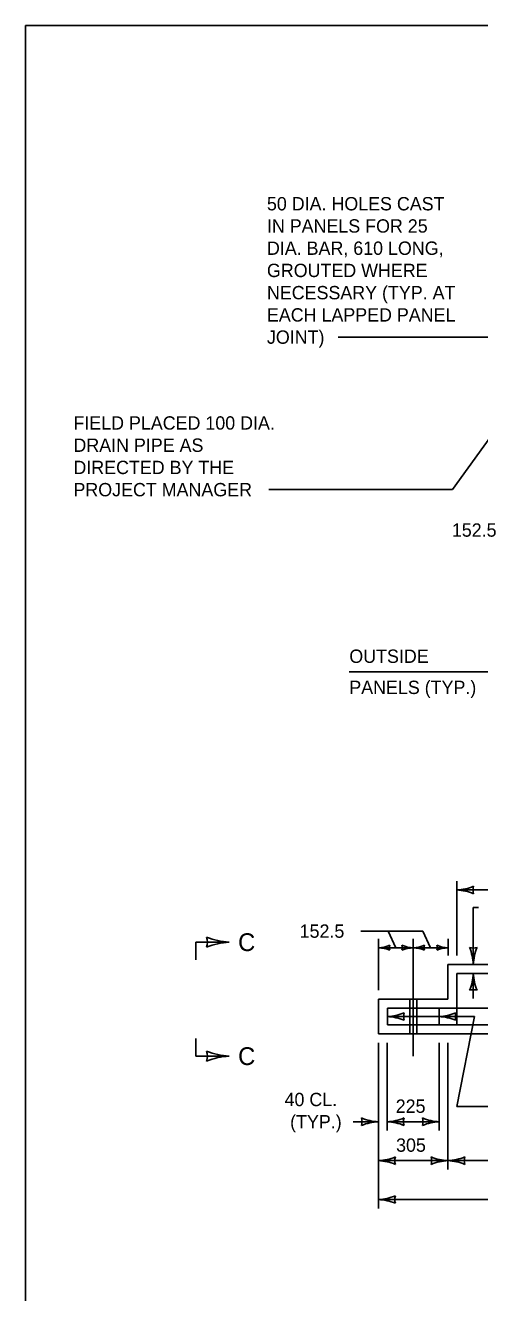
# Model space of a CAD drawing. Extents: x 49991.4 to 50021, y 49987.6 to 50011.4.
# Drawn here: x 49999.38 to 50001.43, y 49993.3 to 49999 of the extents above; entities that cross this region are included whole.
import ezdxf

# ---------------------------------------------------------------- set-up
doc = ezdxf.new("R2010")
doc.units = 0
for name, color, linetype in [('Level 1', 7, 'Continuous'), ('Level 2', 7, 'Continuous'), ('Level 3', 7, 'Continuous'), ('Level 4', 7, 'Continuous'), ('Level 5', 7, 'Continuous'), ('Level 6', 7, 'Continuous')]:
    doc.layers.add(name, color=color, linetype=linetype)

msp = doc.modelspace()

# ---------------------------------------------------------------- linework, layer by layer
at = {"layer": 'Level 1'}
for p, q in [((50003.3142, 49994.7753), (50001.283, 49994.7753)), ((50001.283, 49994.7753), (50001.283, 49994.619)), ((50001.323, 49994.7352), (50001.323, 49994.5029)), ((50003.2741, 49994.7352), (50001.323, 49994.7352)), ((50001.283, 49994.619), (50000.9705, 49994.619)), ((50000.9705, 49994.619), (50000.9705, 49994.4628)), ((50001.0105, 49994.579), (50001.0105, 49994.5029)), ((50001.0105, 49994.579), (50001.6735, 49994.579)), ((50001.2428, 49994.5029), (50001.2428, 49994.579)), ((50000.9705, 49994.4628), (50003.6267, 49994.4628)), ((50001.0105, 49994.5029), (50003.5866, 49994.5029))]:
    msp.add_line(p, q, dxfattribs=at)
msp.add_lwpolyline([(49999.3835, 49998.9992), (50016.7501, 49998.9992), (50016.7501, 49987.7988), (49999.3835, 49987.7988)], close=True, dxfattribs=at)
at = {"layer": 'Level 3'}
for p, q in [((50000.7897, 49997.5969), (50001.6157, 49997.5969)), ((50001.5149, 49997.2046), (50001.3035, 49996.9108)), ((50000.4775, 49996.9108), (50001.3035, 49996.9108)), ((50000.8395, 49996.0916), (50001.7038, 49996.0916)), ((50001.3223, 49994.8153), (50001.3223, 49995.1502)), ((50003.2753, 49995.1102), (50001.3223, 49995.1102)), ((50001.3969, 49995.031), (50001.42, 49995.031)), ((50001.3969, 49994.7753), (50001.3969, 49995.031)), ((50001.17, 49994.9252), (50000.8914, 49994.9252)), ((50001.0136, 49994.9252), (50001.0486, 49994.8502)), ((50001.17, 49994.9252), (50001.205, 49994.8502)), ((50000.9706, 49994.659), (50000.9706, 49994.8902)), ((50001.2832, 49994.8153), (50001.2832, 49994.8902)), ((50001.1268, 49994.8502), (50000.9706, 49994.8502)), ((50001.2832, 49994.8502), (50001.1268, 49994.8502)), ((50001.3969, 49994.6228), (50001.3969, 49994.7352)), ((50001.4028, 49994.541), (50001.0105, 49994.541)), ((50001.4028, 49994.541), (50001.323, 49994.1368)), ((50000.9705, 49994.4228), (50000.9705, 49993.6777)), ((50001.0097, 49994.4228), (50001.0097, 49994.0278)), ((50001.2441, 49994.4228), (50001.2441, 49994.0278)), ((50001.283, 49994.4228), (50001.283, 49993.8527)), ((50001.323, 49994.1368), (50001.5507, 49994.1368)), ((50000.9705, 49994.0678), (50000.8571, 49994.0678)), ((50001.2441, 49994.0678), (50001.0097, 49994.0678)), ((50000.9705, 49993.8927), (50001.283, 49993.8927)), ((50003.3142, 49993.8927), (50001.283, 49993.8927)), ((50003.6267, 49993.7177), (50000.9705, 49993.7177))]:
    msp.add_line(p, q, dxfattribs=at)
for centre, radius, start, end in [((50001.3131, 49995.3323), 0.2223, 272.3605, 292.544), ((50001.3108, 49994.8775), 0.233, 67.9228, 87.1727), ((50001.4505, 49995.1102), 0.0548, 162.1388, 197.8612), ((50000.1287, 49994.8754), 0.073, 342.1388, 17.8612), ((50000.315, 49995.1857), 0.3107, 247.9228, 267.1727), ((50000.3118, 49994.5792), 0.2964, 92.3605, 112.544), ((50000.9645, 49994.9983), 0.1482, 272.3605, 292.544), ((50001.056, 49994.8502), 0.0365, 162.1388, 197.8612), ((50001.0413, 49994.8502), 0.0365, 342.1388, 17.8612), ((50001.1345, 49995.0053), 0.1553, 247.9228, 267.1727), ((50001.1207, 49994.9983), 0.1482, 272.3605, 292.544), ((50001.2123, 49994.8502), 0.0365, 162.1388, 197.8612), ((50001.1977, 49994.8502), 0.0365, 342.1388, 17.8612), ((50001.2908, 49995.0053), 0.1553, 247.9228, 267.1727), ((50000.9629, 49994.6951), 0.1553, 67.9228, 87.1727), ((50001.1329, 49994.7021), 0.1482, 92.3605, 112.544), ((50001.1191, 49994.6951), 0.1553, 67.9228, 87.1727), ((50001.2893, 49994.7021), 0.1482, 92.3605, 112.544), ((50001.3969, 49994.9035), 0.0548, 252.1388, 287.8612), ((50001.1642, 49994.7638), 0.233, 2.8273, 22.0772), ((50001.619, 49994.7661), 0.2223, 157.456, 177.6395), ((50001.1748, 49994.7444), 0.2223, 337.456, 357.6395), ((50001.6296, 49994.7467), 0.233, 182.8273, 202.0772), ((50001.3969, 49994.607), 0.0548, 72.1388, 107.8612), ((50001.0013, 49994.7631), 0.2223, 272.3605, 292.544), ((50000.999, 49994.3083), 0.233, 67.9228, 87.1727), ((50001.1387, 49994.541), 0.0548, 162.1388, 197.8612), ((50001.2336, 49994.7631), 0.2223, 272.3605, 292.544), ((50001.2313, 49994.3083), 0.233, 67.9228, 87.1727), ((50001.371, 49994.541), 0.0548, 162.1388, 197.8612), ((50000.1287, 49994.3628), 0.073, 342.1388, 17.8612), ((50000.315, 49994.6731), 0.3107, 247.9228, 267.1727), ((50000.3118, 49994.0666), 0.2964, 92.3605, 112.544), ((50000.8423, 49994.0678), 0.0548, 342.1388, 17.8612), ((50000.982, 49994.3005), 0.233, 247.9228, 267.1727), ((50000.9797, 49993.8457), 0.2223, 92.3605, 112.544), ((50001.0005, 49994.2899), 0.2223, 272.3605, 292.544), ((50000.9982, 49993.8351), 0.233, 67.9228, 87.1727), ((50001.1379, 49994.0678), 0.0548, 162.1388, 197.8612), ((50001.1159, 49994.0678), 0.0548, 342.1388, 17.8612), ((50001.2556, 49994.3005), 0.233, 247.9228, 267.1727), ((50001.2533, 49993.8457), 0.2223, 92.3605, 112.544), ((50000.9613, 49994.1148), 0.2223, 272.3605, 292.544), ((50000.959, 49993.66), 0.233, 67.9228, 87.1727), ((50001.0987, 49993.8927), 0.0548, 162.1388, 197.8612), ((50001.2922, 49994.1148), 0.2223, 247.456, 267.6395), ((50001.1548, 49993.8927), 0.0548, 342.1388, 17.8612), ((50001.2945, 49993.66), 0.233, 92.8273, 112.0772), ((50001.2715, 49994.1254), 0.233, 272.8273, 292.0772), ((50001.2738, 49993.6706), 0.2223, 67.456, 87.6395), ((50001.4112, 49993.8927), 0.0548, 162.1388, 197.8612), ((50000.9613, 49993.9398), 0.2223, 272.3605, 292.544), ((50001.0987, 49993.7177), 0.0548, 162.1388, 197.8612), ((50000.959, 49993.485), 0.233, 67.9228, 87.1727)]:
    msp.add_arc(centre, radius, start, end, dxfattribs=at)
at = {"layer": 'Level 4'}
for p, q in [((50001.1111, 49994.619), (50001.1111, 49994.4628)), ((50001.1423, 49994.4628), (50001.1423, 49994.619))]:
    msp.add_line(p, q, dxfattribs=at)
at = {"layer": 'Level 5'}
msp.add_line((50001.1268, 49994.8902), (50001.1268, 49994.3628), dxfattribs=at)
at = {"layer": 'Level 6'}
for p, q in [((50000.2996, 49994.8754), (50000.1496, 49994.8754)), ((50000.1496, 49994.8754), (50000.1496, 49994.7954)), ((50000.1496, 49994.4428), (50000.1496, 49994.3628)), ((50000.2996, 49994.3628), (50000.1496, 49994.3628))]:
    msp.add_line(p, q, dxfattribs=at)

# ---------------------------------------------------------------- texts
at = {"layer": 'Level 2'}
for s, height, p in [('50 DIA. HOLES CAST', 0.06, (50000.4693, 49998.1669)), ('IN PANELS FOR 25', 0.06, (50000.4693, 49998.0669)), ('DIA. BAR, 610 LONG,', 0.06, (50000.4693, 49997.9669)), ('GROUTED WHERE', 0.06, (50000.4693, 49997.8669)), ('NECESSARY (TYP. AT', 0.06, (50000.4693, 49997.7669)), ('EACH LAPPED PANEL', 0.06, (50000.4693, 49997.6669)), ('JOINT)', 0.06, (50000.4693, 49997.5669)), ('FIELD PLACED 100 DIA.', 0.06, (49999.5996, 49997.1808)), ('DRAIN PIPE AS ', 0.06, (49999.5996, 49997.0808)), ('DIRECTED BY THE', 0.06, (49999.5996, 49996.9808)), ('PROJECT MANAGER', 0.06, (49999.5996, 49996.8808)), ('152.5', 0.06, (50001.3004, 49996.6991)), ('OUTSIDE', 0.06, (50000.8395, 49996.1316)), ('PANELS (TYP.)', 0.06, (50000.8395, 49995.9916)), ('C', 0.08, (50000.3396, 49994.8354)), ('152.5', 0.06, (50000.6163, 49994.8952)), ('C', 0.08, (50000.3396, 49994.3228)), ('40 CL.', 0.06, (50000.5484, 49994.1378)), ('225', 0.06, (50001.0481, 49994.1078)), ('(TYP.)', 0.06, (50000.5734, 49994.0378)), ('305', 0.06, (50001.0497, 49993.9327))]:
    msp.add_text(s, height=height, dxfattribs=at).set_placement(p)

doc.saveas('drawing.dxf')
